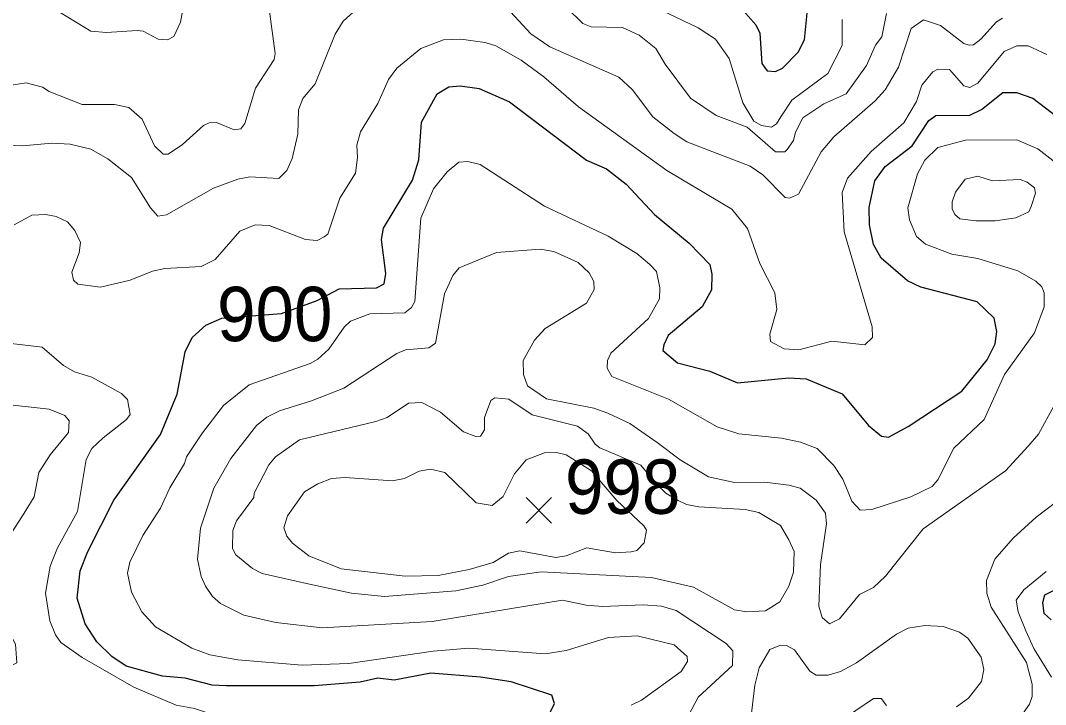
# Model space of a CAD drawing. Extents: x 294.2 to 320.3, y 7482.7 to 7510.7.
# Drawn here: x 316.665 to 318.172, y 7496.053 to 7497.059 of the extents above; entities that cross this region are included whole.
import ezdxf
from ezdxf.enums import TextEntityAlignment as Align

# ---------------------------------------------------------------- set-up
doc = ezdxf.new("R2010")
doc.units = 0
doc.header["$LTSCALE"] = 0.032
for name, color, linetype, lineweight in [('1', 7, 'Continuous', 25), ('2', 7, 'Continuous', 13), ('21', 7, 'Continuous', 25)]:
    doc.layers.add(name, color=color, linetype=linetype, lineweight=lineweight)
doc.layers.add('61', color=7, linetype='Continuous')

msp = doc.modelspace()

# ---------------------------------------------------------------- linework, layer by layer
at = {"layer": '1'}
for points in [[(317.7198, 7497.0824), (317.7458, 7497.0528), (317.7519, 7497.0404), (317.7547, 7496.9958), (317.7625, 7496.985), (317.7747, 7496.984), (317.7852, 7496.9888), (317.808, 7497.0125), (317.8174, 7497.0307), (317.8213, 7497.07)], [(316.7526, 7496.2492), (316.7639, 7496.2779), (316.8021, 7496.3532), (316.8706, 7496.4499), (316.8948, 7496.5095), (316.907, 7496.5714), (316.9169, 7496.5925), (316.9373, 7496.6107), (316.9607, 7496.6212), (317.0484, 7496.628), (317.101, 7496.6469), (317.1334, 7496.6643), (317.188, 7496.6658), (317.1993, 7496.6719), (317.2016, 7496.687), (317.1955, 7496.7368), (317.1986, 7496.7534), (317.2412, 7496.8244), (317.2504, 7496.8539), (317.2541, 7496.9097), (317.2772, 7496.9514), (317.2944, 7496.9616), (317.311, 7496.9629), (317.3391, 7496.9591), (317.3838, 7496.9393), (317.4968, 7496.8536), (317.5263, 7496.8408), (317.5554, 7496.8181), (317.597, 7496.7736), (317.6476, 7496.7313), (317.6782, 7496.7003), (317.6813, 7496.686), (317.6805, 7496.6626), (317.6669, 7496.6376), (317.6171, 7496.5954), (317.6107, 7496.5818), (317.6092, 7496.5735), (317.6304, 7496.5554), (317.678, 7496.5433), (317.7188, 7496.5259), (317.794, 7496.5334), (317.8197, 7496.5319), (317.8729, 7496.51), (317.9115, 7496.4632), (317.9304, 7496.4473), (317.9409, 7496.4458), (317.9696, 7496.4617), (318.0486, 7496.5138), (318.0857, 7496.5598), (318.0978, 7496.5833), (318.1001, 7496.6014), (318.0963, 7496.621), (318.0714, 7496.6452), (317.9883, 7496.667), (317.9687, 7496.6761), (317.9303, 7496.7093), (317.919, 7496.7297), (317.9129, 7496.7584), (317.9122, 7496.7841), (317.9207, 7496.8231), (317.9361, 7496.8441), (317.9757, 7496.8748), (318, 7496.9118), (318.0106, 7496.9194), (318.0604, 7496.9201), (318.0778, 7496.9284), (318.1092, 7496.9534), (318.1289, 7496.9534), (318.1531, 7496.9451), (318.2173, 7496.896)], [(316.8733, 7496.0944), (316.8201, 7496.1088), (316.7989, 7496.1231), (316.777, 7496.145), (316.7597, 7496.1714), (316.748, 7496.2092), (316.7526, 7496.2492)], [(318.2004, 7496.2286), (318.1702, 7496.2135), (318.1671, 7496.2022), (318.1693, 7496.1871), (318.1799, 7496.1773)], [(317.443, 7496.0399), (317.4498, 7496.0543), (317.446, 7496.0664), (317.3863, 7496.086), (317.341, 7496.0928), (317.2678, 7496.0988), (317.2142, 7496.0883), (317.1903, 7496.0914), (317.1642, 7496.0856), (317.0965, 7496.0801), (316.967, 7496.0801), (316.9466, 7496.0809), (316.9066, 7496.0914), (316.8733, 7496.0944)]]:
    msp.add_lwpolyline(points, dxfattribs=at)
at = {"layer": '2'}
for points in [[(316.6891, 7497.0919), (316.7683, 7497.0434), (316.7913, 7497.0414), (316.836, 7497.0447), (316.8449, 7497.0434), (316.8672, 7497.0319), (316.8807, 7497.0306), (316.8902, 7497.0357), (316.8998, 7497.0568), (316.9209, 7497.1742)], [(316.6074, 7496.8774), (316.6674, 7496.8748), (316.7108, 7496.8787), (316.7377, 7496.8774), (316.7683, 7496.8697), (316.7932, 7496.8557), (316.8277, 7496.8282), (316.8558, 7496.7835), (316.8666, 7496.7714), (316.8794, 7496.7733), (316.9484, 7496.8123), (316.9841, 7496.8256), (317.002, 7496.8289), (317.0447, 7496.8269), (317.0562, 7496.8384), (317.0639, 7496.8563), (317.0722, 7496.8921), (317.0735, 7496.9278), (317.0798, 7496.9444), (317.0977, 7496.9661), (317.1271, 7497.0389), (317.1392, 7497.058), (317.1584, 7497.0753)], [(316.6482, 7496.9636), (316.6731, 7496.9674), (316.6968, 7496.961), (316.707, 7496.9546), (316.7555, 7496.9355), (316.8028, 7496.9355), (316.8238, 7496.931), (316.8436, 7496.9138), (316.8615, 7496.8748), (316.8743, 7496.8627), (316.8819, 7496.8627), (316.903, 7496.8767), (316.9336, 7496.9048), (316.942, 7496.9086), (316.9528, 7496.9093), (316.979, 7496.8984), (316.9886, 7496.8997), (316.9943, 7496.9074), (317.0103, 7496.9597), (317.0377, 7497.0019), (317.039, 7497.0108), (317.03, 7497.0798)], [(317.3735, 7497.0849), (317.415, 7497.0395), (317.4431, 7497.0204), (317.5446, 7496.9757), (317.5645, 7496.9572), (317.5945, 7496.9176), (317.6256, 7496.8928), (317.6445, 7496.8806), (317.7375, 7496.8448), (317.756, 7496.832), (317.7891, 7496.7985), (317.7954, 7496.7979), (317.8086, 7496.8035), (317.8419, 7496.8659), (317.8603, 7496.8882), (317.9213, 7496.9412), (317.9361, 7496.9572), (317.9558, 7496.9904), (317.9744, 7497.0472), (317.9922, 7497.06), (318.0172, 7497.0517), (318.0516, 7497.0255), (318.0593, 7497.0229), (318.0657, 7497.0235), (318.0765, 7497.0319), (318.0995, 7497.0574), (318.1084, 7497.0625)], [(317.4674, 7497.0785), (317.4917, 7497.0548), (317.5038, 7497.0498), (317.5498, 7497.0491), (317.5741, 7497.0376), (317.5986, 7497.0182), (317.6124, 7496.9948), (317.6497, 7496.9447), (317.6876, 7496.9194), (317.7329, 7496.9022), (317.7748, 7496.8657), (317.7886, 7496.8657), (317.7921, 7496.8691), (317.8012, 7496.8824), (317.8041, 7496.8947), (317.815, 7496.9159), (317.846, 7496.9365), (317.8786, 7496.9514), (317.9086, 7496.9929), (317.922, 7497.0229), (317.931, 7497.0351), (317.9379, 7497.0696)], [(317.5944, 7497.0804), (317.661, 7497.0485), (317.6863, 7497.0318), (317.7064, 7497.0031), (317.7265, 7496.938), (317.7431, 7496.9112), (317.754, 7496.9046), (317.769, 7496.9023), (317.7764, 7496.9073), (317.7828, 7496.9174), (317.7988, 7496.9419), (317.8518, 7496.9814), (317.8728, 7497.0223), (317.8728, 7497.0606)], [(317.9833, 7496.8333), (317.9941, 7496.8537), (318.0133, 7496.8723), (318.0542, 7496.8831), (318.1295, 7496.8838), (318.1602, 7496.8703), (318.1825, 7496.8531), (318.2394, 7496.8039), (318.2693, 7496.788), (318.3011, 7496.7778), (318.328, 7496.7631), (318.3355, 7496.762), (318.3499, 7496.7647), (318.3539, 7496.7703), (318.3613, 7496.8121), (318.3694, 7496.8227), (318.3837, 7496.8288), (318.459, 7496.8448), (318.496, 7496.8627), (318.5171, 7496.8857), (318.5356, 7496.9163), (318.5452, 7496.9457), (318.5554, 7496.9942), (318.5924, 7497.0823)], [(316.6553, 7496.7586), (316.6815, 7496.7727), (316.7019, 7496.7739), (316.7172, 7496.7707), (316.7338, 7496.763), (316.7447, 7496.7503), (316.7529, 7496.7324), (316.7511, 7496.7171), (316.7402, 7496.689), (316.7427, 7496.6769), (316.7492, 7496.6711), (316.7824, 7496.6667), (316.8258, 7496.6769), (316.859, 7496.6903), (316.8768, 7496.6941), (316.9305, 7496.6973), (316.9509, 7496.7075), (316.9873, 7496.749), (317.0096, 7496.7586), (317.0301, 7496.7573), (317.0837, 7496.7369), (317.1009, 7496.7356), (317.1112, 7496.7407), (317.1163, 7496.7446), (317.1341, 7496.7976), (317.1571, 7496.8346), (317.1603, 7496.8576), (317.159, 7496.8755), (317.1648, 7496.8952), (317.1903, 7496.9368), (317.2057, 7496.9725), (317.2178, 7496.9891), (317.2535, 7497.0178), (317.2867, 7497.0306), (317.3123, 7497.0319), (317.348, 7497.0268), (317.3634, 7497.0217), (317.401, 7497.0006), (317.4342, 7496.9763), (317.4853, 7496.9323), (317.6149, 7496.8384), (317.7107, 7496.7816), (317.7336, 7496.7529), (317.7515, 7496.7018), (317.7739, 7496.6584), (317.7765, 7496.6341), (317.7662, 7496.5977), (317.7675, 7496.5868), (317.7873, 7496.576), (317.809, 7496.5747), (317.8575, 7496.5875), (317.906, 7496.5817), (317.9175, 7496.5926), (317.9169, 7496.6086), (317.8756, 7496.7481), (317.8727, 7496.8062), (317.8808, 7496.8274), (317.9152, 7496.8664), (317.9634, 7496.9084), (317.9818, 7496.9401), (317.9898, 7496.9641), (318.0059, 7496.9836), (318.0133, 7496.9878), (318.0305, 7496.9872), (318.0516, 7496.9629), (318.0606, 7496.9604), (318.0721, 7496.9668), (318.111, 7497.0134), (318.1295, 7497.0217), (318.1461, 7497.0217), (318.1736, 7497.0089)], [(317.5626, 7496.0518), (317.5779, 7496.0588), (317.636, 7496.101), (317.6455, 7496.1157), (317.6449, 7496.1233), (317.6258, 7496.1405), (317.5715, 7496.1539), (317.5294, 7496.1514), (317.4668, 7496.1322), (317.4362, 7496.1271), (317.3238, 7496.1355), (317.2714, 7496.131), (317.1476, 7496.1131), (317.0786, 7496.1105), (316.9841, 7496.1182), (316.9432, 7496.1258), (316.9164, 7496.1355), (316.8634, 7496.1667), (316.843, 7496.1891), (316.8277, 7496.2178), (316.8221, 7496.246), (316.8255, 7496.2622), (316.8444, 7496.3011), (316.8703, 7496.3415), (316.8841, 7496.3716), (316.9059, 7496.4072), (316.9087, 7496.417), (316.9324, 7496.4522), (316.963, 7496.4924), (317.0007, 7496.523), (317.0907, 7496.5543), (317.1016, 7496.5607), (317.1182, 7496.5754), (317.1405, 7496.6079), (317.1501, 7496.6169), (317.1782, 7496.6277), (317.2299, 7496.629), (317.2395, 7496.6367), (317.2446, 7496.6456), (317.2535, 7496.7682), (317.2721, 7496.8116), (317.2918, 7496.8365), (317.3091, 7496.8506), (317.3225, 7496.8518), (317.3404, 7496.8473), (317.4349, 7496.786), (317.5287, 7496.742), (317.5708, 7496.7165), (317.5893, 7496.7005), (317.5996, 7496.6896), (317.6047, 7496.666), (317.6041, 7496.6494), (317.5881, 7496.6207), (317.5324, 7496.5694), (317.5278, 7496.5588), (317.5272, 7496.5477), (317.5341, 7496.5354), (317.6175, 7496.502), (317.689, 7496.4611), (317.7209, 7496.4509), (317.7835, 7496.4445), (317.8116, 7496.4387), (317.8358, 7496.4292), (317.8607, 7496.4042), (317.8735, 7496.3844), (317.8869, 7496.3519), (317.899, 7496.3385), (317.9163, 7496.3398), (317.9737, 7496.3583), (318.005, 7496.3736), (318.0133, 7496.3832), (318.0369, 7496.4298), (318.0816, 7496.4719), (318.1116, 7496.5384), (318.1557, 7496.5996), (318.1698, 7496.638), (318.1698, 7496.6584), (318.1665, 7496.6673), (318.1576, 7496.6756), (318.1308, 7496.6909), (318.0721, 7496.7088)], [(318.0721, 7496.7088), (318.0338, 7496.7152), (317.9955, 7496.7299), (317.982, 7496.7414), (317.9718, 7496.7656), (317.9693, 7496.7835), (317.9833, 7496.8333)], [(317.0403, 7496.1731), (316.993, 7496.184), (316.9585, 7496.2012), (316.9471, 7496.2114), (316.9368, 7496.2268), (316.9304, 7496.2408), (316.9247, 7496.2664), (316.9292, 7496.3123), (316.949, 7496.3711), (316.9739, 7496.4145), (317.0115, 7496.463), (317.0268, 7496.4757), (317.0454, 7496.4847), (317.0927, 7496.4994), (317.1399, 7496.5179), (317.2178, 7496.569), (317.2306, 7496.5747), (317.265, 7496.5773), (317.2746, 7496.5843), (317.288, 7496.6571), (317.3001, 7496.6839), (317.3097, 7496.6954), (317.3646, 7496.7178), (317.4285, 7496.7229), (317.4489, 7496.719), (317.4847, 7496.703), (317.5006, 7496.6877), (317.5076, 7496.675), (317.5083, 7496.6635), (317.4968, 7496.6431), (317.4362, 7496.606), (317.4202, 7496.5888), (317.4036, 7496.5587), (317.4042, 7496.5384), (317.41, 7496.5218), (317.4381, 7496.5026), (317.5077, 7496.4885), (317.5281, 7496.4815), (317.5606, 7496.4662), (317.6009, 7496.4381), (317.6347, 7496.4126), (317.6762, 7496.3876), (317.7145, 7496.3794), (317.7592, 7496.38), (317.7943, 7496.3755), (317.8109, 7496.371), (317.8345, 7496.3532), (317.848, 7496.334), (317.8498, 7496.3187), (317.8409, 7496.2587), (317.8383, 7496.1974), (317.8435, 7496.1808), (317.8543, 7496.1712), (317.869, 7496.1789), (317.8984, 7496.2146), (317.9188, 7496.2249), (317.9367, 7496.2415), (317.9916, 7496.311), (318.1129, 7496.3963), (318.1461, 7496.433), (318.1615, 7496.4502), (318.1844, 7496.4924)], [(316.7159, 7496.1553), (316.7076, 7496.1757), (316.7013, 7496.2166), (316.7082, 7496.2561), (316.7191, 7496.283), (316.7485, 7496.3366), (316.7613, 7496.4132), (316.7696, 7496.4292), (316.7862, 7496.4451), (316.8206, 7496.4719), (316.8257, 7496.4796), (316.8219, 7496.5013), (316.813, 7496.5102), (316.7696, 7496.5345), (316.744, 7496.5421), (316.7281, 7496.5517), (316.6967, 7496.5786), (316.6508, 7496.5837)], [(316.5237, 7496.0486), (316.5512, 7496.0646), (316.578, 7496.0959), (316.5985, 7496.1125), (316.6163, 7496.1156), (316.6483, 7496.1086), (316.6591, 7496.1137), (316.6572, 7496.1412), (316.638, 7496.177), (316.6278, 7496.2127), (316.6431, 7496.2625), (316.6489, 7496.3014), (316.6699, 7496.334), (316.6847, 7496.3583), (316.6917, 7496.3941), (316.7082, 7496.4202), (316.7351, 7496.4528), (316.7363, 7496.47), (316.73, 7496.4777), (316.707, 7496.4872), (316.5512, 7496.5045)], [(318.233, 7496.3851), (318.1582, 7496.3283), (318.1244, 7496.2976), (318.097, 7496.2663), (318.0848, 7496.235), (318.0855, 7496.2166), (318.0919, 7496.1961), (318.1436, 7496.1144), (318.1519, 7496.0825), (318.1519, 7496.0646), (318.148, 7496.0531), (318.1353, 7496.0352)], [(318.1725, 7496.2481), (318.1397, 7496.2214), (318.1288, 7496.2063), (318.1317, 7496.1888), (318.1426, 7496.161), (318.1547, 7496.1348), (318.1806, 7496.0927)], [(317.5804, 7496.1993), (317.5204, 7496.1968), (317.4962, 7496.1986), (317.4617, 7496.2063), (317.2701, 7496.175), (317.108, 7496.1654), (317.0403, 7496.1731)], [(317.6468, 7496.0365), (317.6609, 7496.0633), (317.7113, 7496.1099), (317.7119, 7496.1316), (317.7024, 7496.1425), (317.6289, 7496.191), (317.6073, 7496.1974), (317.5804, 7496.1993)], [(317.7387, 7496.0314), (317.7445, 7496.0812), (317.7509, 7496.1067), (317.7662, 7496.1336), (317.7822, 7496.1399), (317.7911, 7496.1393), (317.8026, 7496.1329), (317.825, 7496.1016), (317.8346, 7496.0959), (317.8524, 7496.0959), (317.8703, 7496.101), (317.8939, 7496.1138), (317.9526, 7496.1559), (317.9699, 7496.1648), (317.9942, 7496.1687)], [(317.9942, 7496.1687), (318.021, 7496.1674), (318.0453, 7496.1591), (318.0574, 7496.1501), (318.0771, 7496.1221), (318.081, 7496.1042), (318.0778, 7496.0863)], [(316.9668, 7496.0314), (316.9203, 7496.0467), (316.8934, 7496.0518), (316.8315, 7496.078), (316.7555, 7496.122), (316.7242, 7496.1437), (316.7159, 7496.1553)], [(318.0778, 7496.0863), (318.0587, 7496.062), (318.0408, 7496.0492)], [(317.8671, 7496.0262), (317.9188, 7496.0614), (317.9303, 7496.0614), (317.9379, 7496.0512)]]:
    msp.add_lwpolyline(points, dxfattribs=at)
for points in [[(318.1505, 7496.7854), (318.1474, 7496.7777), (318.1283, 7496.7688), (318.0976, 7496.7643), (318.0695, 7496.7643), (318.0459, 7496.7675), (318.0382, 7496.7739), (318.0344, 7496.7822), (318.0344, 7496.7925), (318.0395, 7496.8065), (318.0535, 7496.8256), (318.0721, 7496.8301), (318.0938, 7496.8231), (318.1346, 7496.825), (318.1449, 7496.8212), (318.1557, 7496.8129), (318.157, 7496.8052)], [(317.7943, 7496.295), (317.7822, 7496.3162), (317.7503, 7496.3353), (317.7299, 7496.3398), (317.6622, 7496.3436), (317.6441, 7496.347), (317.6318, 7496.353), (317.6135, 7496.3637), (317.5991, 7496.3772), (317.5769, 7496.4046), (317.5166, 7496.4304), (317.5095, 7496.4355), (317.4993, 7496.4509), (317.4834, 7496.4624), (317.417, 7496.479), (317.3825, 7496.502), (317.3621, 7496.5038), (317.3563, 7496.5), (317.3467, 7496.4751), (317.3467, 7496.4566), (317.341, 7496.4476), (317.334, 7496.447), (317.3161, 7496.454), (317.2823, 7496.4828), (317.2548, 7496.4968), (317.235, 7496.4962), (317.2037, 7496.4751), (317.1871, 7496.4693), (317.0748, 7496.4419), (317.0396, 7496.417), (317.03, 7496.4055), (317.0083, 7496.3634), (317.0077, 7496.357), (316.9822, 7496.3231), (316.9771, 7496.3085), (316.9764, 7496.2823), (316.9815, 7496.2727), (317.0058, 7496.2529), (317.0199, 7496.2453), (317.0939, 7496.2287), (317.1514, 7496.2165), (317.1999, 7496.2114), (317.3046, 7496.2197), (317.3442, 7496.228), (317.382, 7496.2411), (317.4304, 7496.2478), (317.5924, 7496.2397), (317.654, 7496.2252), (317.7145, 7496.1917), (317.7324, 7496.1891), (317.7601, 7496.1907), (317.7809, 7496.2037), (317.7943, 7496.2268), (317.8013, 7496.2472), (317.802, 7496.2779)], [(317.3595, 7496.2618), (317.3243, 7496.2511), (317.2788, 7496.2424), (317.2304, 7496.2414), (317.1361, 7496.2523), (317.0888, 7496.2714), (317.0645, 7496.2899), (317.0561, 7496.3001), (317.0517, 7496.3124), (317.0572, 7496.3302), (317.0821, 7496.3656), (317.1016, 7496.3775), (317.1221, 7496.385), (317.1421, 7496.3866), (317.2114, 7496.3819), (317.2293, 7496.3851), (317.251, 7496.396), (317.2676, 7496.3991), (317.2886, 7496.394), (317.3346, 7496.3493), (317.3582, 7496.3455), (317.3742, 7496.3589), (317.3908, 7496.3921), (317.408, 7496.4126), (317.4349, 7496.4228), (317.4528, 7496.4234), (317.4668, 7496.4202), (317.5043, 7496.3967), (317.5415, 7496.3526), (317.5811, 7496.3155), (317.5849, 7496.3091), (317.5817, 7496.2906), (317.5709, 7496.2791), (317.5626, 7496.2772), (317.5396, 7496.2759), (317.4975, 7496.2834), (317.4669, 7496.2715), (317.4519, 7496.2688), (317.3987, 7496.279), (317.382, 7496.2753)]]:
    msp.add_lwpolyline(points, close=True, dxfattribs=at)
at = {"layer": '21'}
for p, q in [((317.408, 7496.3571), (317.4455, 7496.3196)), ((317.4455, 7496.3571), (317.408, 7496.3196))]:
    msp.add_line(p, q, dxfattribs=at)

# ---------------------------------------------------------------- texts
at = {"layer": '61', "width": 0.95}
for s, p in [('900', (317.0385, 7496.5873)), ('998', (317.5501, 7496.3332))]:
    msp.add_text(s, height=0.08, dxfattribs=at).set_placement(p, align=Align.CENTER)

doc.saveas('drawing.dxf')
